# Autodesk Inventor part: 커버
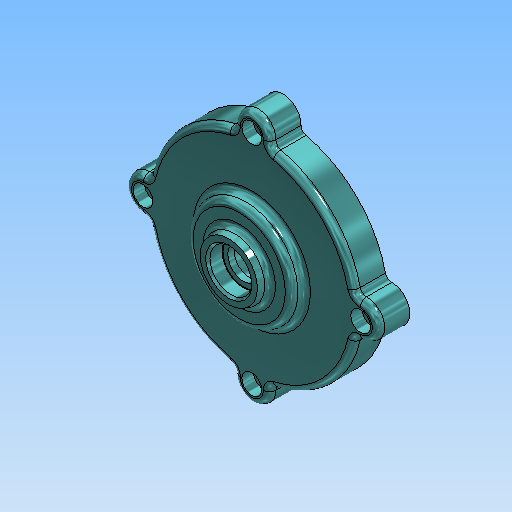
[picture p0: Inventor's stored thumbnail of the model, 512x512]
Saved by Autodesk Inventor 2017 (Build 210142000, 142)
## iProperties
Created: 2021-07
Part Number: 커버
Document SubType Name: 모델링
Designer: mdu
Material: 알루미늄 6061
Density: 2.71 g/cm^3
Mass: 196.659 g
Surface Area: 278.607 cm^2
Volume: 72.5678 cm^3
Appearance: 커버
변환 표준: STEP AP214IS
파일 이름: C:\Users\SeoGD\Desktop\?쒗뿕\而ㅻ쾭-1.stp
전처리기: Build: 253, Release: 2010 SP1 - Date: Wed 07/29/2009
전송 단위: 밀리미터
불확실성: 0.01
Author: mdu
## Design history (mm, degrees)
sketch "스케치1"
  geometry: L1 (0, 0)-(0, 26); L2 (50, 0)-(50, 15); L3 (50, 15)-(25, 15); L4 (25, 15)-(25, 21); L5 (25, 21)-(15, 21); L6 (15, 21)-(13.66, 26); L7 (13.66, 26)-(10, 26); L8 (50, 0)-(45, 0); L9 (45, 0)-(45, 10); L10 (45, 10)-(14.5, 10); L11 (14.5, 10)-(13.266, 3); L12 (13.266, 3)-(11, 3); L13 (11, 3)-(11, 16); L14 (11, 16)-(7.5, 16); L15 (7.5, 16)-(7.5, 19); L16 (7.5, 19)-(10, 19); L17 (10, 19)-(10, 26)
  constraints: 34 end point, 10 parallel, 2 perpendicular, 2 point on line, 1 vertical
  dimensions: "d11" = 100 diameter of L2 L1; "d12" = 22 diameter of L13 L1; "d13" = 90 diameter of L9 L1; "d14" = 15 distance between parallel lines of L3 L8; "d15" = 10 distance between parallel lines of L8 L10; "d16" = 29 diameter of L10.end L1; "d17" = 100 deg angle of L11 L10; "d18" = 7 distance between parallel lines of L12 L10; "d19" = 13 distance between parallel lines of L14 L12; "d20" = 3 distance between parallel lines of L16 L14; "d21" = 15 diameter of L15 L1; "d22" = 20 diameter of L17 L1; "d23" = 30 diameter of L5.end L1; "d24" = 6 distance between parallel lines of L5 L3; "d25" = 50 diameter of L4 L1; "d26" = 105 deg angle of L5 L6; "d50" = 26 distance of L1.start L1.end
revolve "회전1" sketch "스케치1" stored, may be unused: angle "d27" = 90 deg
sketch "스케치2" dims "d29" = 104
  geometry: A1 r 8.5 centre (0, 52) between (8.074, 49.344) and (-8.074, 49.344); A2 r 50 centre (0, 0) between (-8.074, 49.344) and (8.074, 49.344) reference; 2 further points
  constraints: 4 point on circle, 2 vertical alignment, 1 centre point, 1 coincident, 2 other
  dimensions: "d28" = 17 diameter of A1
extrude "돌출1" join sketch "스케치2" stored distance "d30" = 10; taper "d31" = 0 deg
fillet "모깎기3" dims "d32" = 3
fillet "모깎기4" dims "d45" = 3, "d46" = 0.2
chamfer "모따기1" distance "d47" = 1; stored, may be unused: second distance "d48" = 2, angle "d49" = 45 deg
hole "구멍2" diameter "d38" = 5.5; stored, may be unused: countersink angle "d42" = 90 deg, drill point angle "d44" = 118 deg; dims "d36" = 10, "d37" = 10, "d39" = 6, "d40" = 9.5, "d41" = 5.4, "d43" = 8
node "솔리드1"
node "솔리드 본체"
node "곡면 본체"
pattern_circular "원형 패턴1" dims angle "d34" = 360 deg
pattern_circular "원형 패턴2" dims angle "d52" = 360 deg
node "솔리드2"
